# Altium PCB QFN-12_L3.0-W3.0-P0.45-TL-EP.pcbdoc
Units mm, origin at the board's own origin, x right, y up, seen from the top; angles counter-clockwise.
Board outline 16.21 x 15.87 mm, 2 copper layers (Top Layer, Bottom Layer), stack 0 mm thick; 1 components, 0 nets, 12 pads, 0 vias.
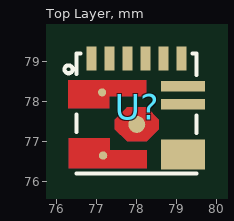
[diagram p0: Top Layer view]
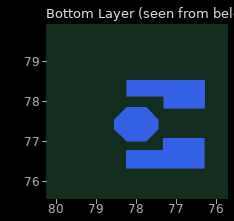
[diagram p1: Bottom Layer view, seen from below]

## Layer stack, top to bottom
Top Layer: signal copper (thickness not stored)
Bottom Layer: signal copper (thickness not stored)

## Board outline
86.056,69.85 69.85,69.85 69.85,85.724 86.056,85.724

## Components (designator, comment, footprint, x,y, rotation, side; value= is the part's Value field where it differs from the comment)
U? "" QFN-12_L3.0-W3.0-P0.45-TL-EP 78.015,77.873 r0 top

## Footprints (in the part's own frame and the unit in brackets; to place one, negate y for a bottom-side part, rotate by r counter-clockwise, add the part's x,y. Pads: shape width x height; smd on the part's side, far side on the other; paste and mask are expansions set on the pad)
QFN-12_L3.0-W3.0-P0.45-TL-EP [mm]
  round 0.205 smd: 1(-0.878,0.351)
  round 0.425 smd: 2(-0.01,-0.45)
  round 0.21 smd: 3(-0.853,-1.229)
  rect 1.1x0.75 smd paste-100 mask+0.05: 4(1.14,-1.198)
  rect 1.1x0.26 smd paste-100 mask+0.05: 5(1.14,0.052) 6(1.14,0.502)
  rect 0.25x0.6 smd paste-100 mask+0.05: 7(1.109,1.201) 8(0.66,1.201) 9(0.21,1.201) 10(-0.241,1.201) 11(-0.69,1.201) 12(-1.14,1.201)
  Top Layer region: -1.72,0.65 0.229,0.65 0.229,0.251 -0.699,0.251 -0.699,-0.051 -1.721,-0.051 -1.721,0.249
  Top Layer region: -1.706,-1.551 0.243,-1.551 0.243,-1.103 -0.685,-1.103 -0.685,-0.8 -1.707,-0.8 -1.707,-1.15
  Top Layer region: -0.256,-0.025 0.235,-0.025 0.54,-0.33 0.54,-0.571 0.235,-0.875 -0.254,-0.875 -0.56,-0.57 -0.56,-0.33 -0.267,-0.038
  Bottom Layer region: -1.72,0.65 0.229,0.65 0.229,0.251 -0.699,0.251 -0.699,-0.051 -1.721,-0.051 -1.721,0.249
  Bottom Layer region: -1.706,-1.551 0.243,-1.551 0.243,-1.103 -0.685,-1.103 -0.685,-0.8 -1.707,-0.8 -1.707,-1.15
  Bottom Layer region: -0.256,-0.025 0.235,-0.025 0.54,-0.33 0.54,-0.571 0.235,-0.875 -0.254,-0.875 -0.56,-0.57 -0.56,-0.33 -0.267,-0.038
  Multi-Layer region: -1.72,0.65 0.229,0.65 0.229,0.251 -0.699,0.251 -0.699,-0.051 -1.721,-0.051 -1.721,0.249
  Multi-Layer region: -1.706,-1.551 0.243,-1.551 0.243,-1.103 -0.685,-1.103 -0.685,-0.8 -1.707,-0.8 -1.707,-1.15
  Multi-Layer region: -0.256,-0.025 0.235,-0.025 0.54,-0.33 0.54,-0.571 0.235,-0.875 -0.254,-0.875 -0.56,-0.57 -0.56,-0.33 -0.267,-0.038
  silkscreen extent -1.81,-1.67 1.48,1.33

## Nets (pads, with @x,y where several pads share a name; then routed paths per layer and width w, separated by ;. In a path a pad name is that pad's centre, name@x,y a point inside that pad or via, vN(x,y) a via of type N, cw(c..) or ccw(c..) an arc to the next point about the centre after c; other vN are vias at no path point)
pads on no net: U?.1 U?.2 U?.3 U?.4 U?.5 U?.6 U?.7 U?.8 U?.9 U?.10 U?.11 U?.12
